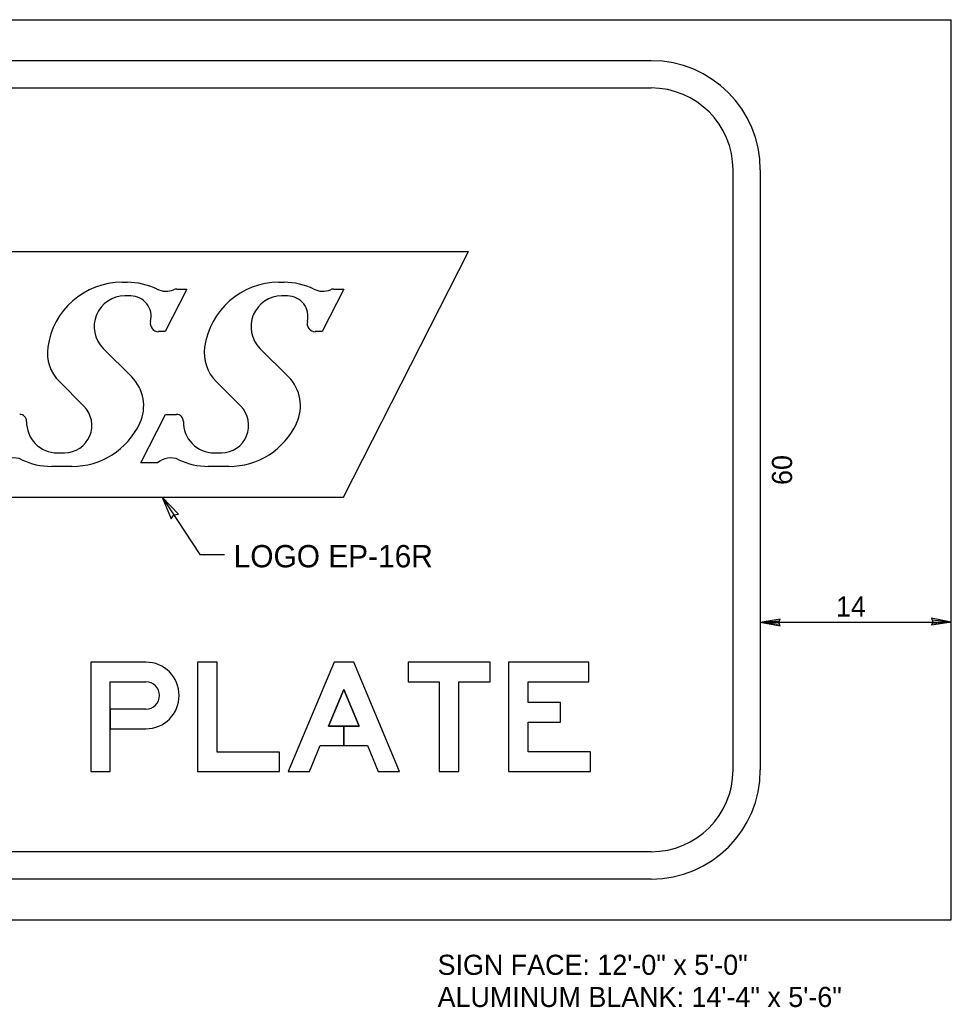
# Model space of a CAD drawing. Extents: x 60714 to 61340, y 9180 to 9758.
# Drawn here: x 60952.6 to 61082.4, y 9609.1 to 9746.7 of the extents above; entities that cross this region are included whole.
import ezdxf

# ---------------------------------------------------------------- set-up
doc = ezdxf.new("R2010")
doc.units = 0
for name, color, linetype in [('1', 7, 'Continuous'), ('2', 7, 'Continuous'), ('52', 7, 'Continuous'), ('GSBWFill', 7, 'Continuous'), ('SignPanel', 7, 'Continuous')]:
    doc.layers.add(name, color=color, linetype=linetype)

msp = doc.modelspace()

# ---------------------------------------------------------------- linework, layer by layer
at = {"layer": '1'}
for p, q in [((60972.45, 9680.2), (60977.68, 9672.2)), ((60977.68, 9672.2), (60981.12, 9672.2)), ((61055.78, 9662.78), (61082.38, 9662.78))]:
    msp.add_line(p, q, dxfattribs=at)
at = {"layer": '2'}
for p, q in [((60755.58, 9746.7), (61082.38, 9746.7)), ((61082.38, 9621.3), (61082.38, 9746.7)), ((60755.58, 9621.3), (61082.38, 9621.3))]:
    msp.add_line(p, q, dxfattribs=at)
at = {"layer": '52'}
for p, q in [((60972.45, 9680.2), (60973.69, 9677.16)), ((60974.71, 9677.83), (60972.45, 9680.2)), ((60973.69, 9677.16), (60974.08, 9677.71)), ((60974.08, 9677.71), (60974.71, 9677.83)), ((61055.78, 9662.78), (61058.56, 9663.22)), ((61058.34, 9662.73), (61058.56, 9663.22)), ((61082.38, 9662.78), (61079.62, 9663.31)), ((61079.62, 9663.31), (61079.83, 9662.82)), ((61055.78, 9662.78), (61058.44, 9662.96)), ((61055.78, 9662.78), (61058.54, 9662.24)), ((61055.78, 9662.78), (61058.44, 9662.5)), ((61058.54, 9662.24), (61058.34, 9662.73)), ((61079.83, 9662.82), (61079.61, 9662.34)), ((61082.38, 9662.78), (61079.61, 9662.34)), ((61082.38, 9662.78), (61079.72, 9662.59)), ((61082.38, 9662.78), (61079.73, 9663.06))]:
    msp.add_line(p, q, dxfattribs=at)
at = {"layer": 'GSBWFill'}
for p, q in [((60965.22, 9654.46), (60970.17, 9654.46)), ((60965.22, 9654.46), (60970.17, 9654.46)), ((60965.22, 9654.46), (60970.17, 9654.46)), ((60965.22, 9647.92), (60970.17, 9647.92))]:
    msp.add_line(p, q, dxfattribs=at)
for points in [[(60970.17, 9657.2), (60962.49, 9657.2), (60962.49, 9641.99), (60965.22, 9641.99), (60965.22, 9647.92)], [(60970.17, 9657.2), (60962.49, 9657.2), (60962.49, 9641.99), (60965.22, 9641.99), (60965.22, 9654.46)], [(60970.17, 9657.2), (60962.49, 9657.2), (60962.49, 9641.99), (60965.22, 9641.99), (60965.22, 9654.46)], [(60970.17, 9650.66), (60965.22, 9650.66), (60965.22, 9654.46)], [(60970.17, 9650.66), (60965.22, 9650.66), (60965.22, 9647.92), (60970.17, 9647.92)], [(60970.17, 9650.66), (60965.22, 9650.66), (60965.22, 9647.92), (60970.17, 9647.92)]]:
    msp.add_lwpolyline(points, dxfattribs=at)
for points in [[(60988.79, 9641.99), (60988.79, 9644.65), (60980.12, 9644.65), (60980.12, 9657.2), (60977.39, 9657.2), (60977.39, 9641.99)], [(60988.79, 9641.99), (60988.79, 9644.65), (60980.12, 9644.65), (60980.12, 9657.2), (60977.39, 9657.2), (60977.39, 9641.99)], [(60988.79, 9641.99), (60988.79, 9644.65), (60980.12, 9644.65), (60980.12, 9657.2), (60977.39, 9657.2), (60977.39, 9641.99)], [(60994.47, 9645.57), (61001.04, 9645.57), (61002.55, 9641.99), (61005.51, 9641.99), (60999.13, 9657.2), (60996.39, 9657.2), (60990.01, 9641.99), (60992.97, 9641.99)], [(60999.9, 9648.3), (60997.76, 9648.3), (60997.76, 9645.57), (61001.04, 9645.57), (61002.55, 9641.99), (61005.51, 9641.99), (60999.13, 9657.2), (60996.39, 9657.2), (60990.01, 9641.99), (60992.97, 9641.99), (60994.47, 9645.57), (60997.76, 9645.57), (60997.76, 9648.3), (60995.62, 9648.3), (60997.76, 9653.39)], [(60999.9, 9648.3), (60997.76, 9648.3), (60997.76, 9645.57), (61001.04, 9645.57), (61002.55, 9641.99), (61005.51, 9641.99), (60999.13, 9657.2), (60996.39, 9657.2), (60990.01, 9641.99), (60992.97, 9641.99), (60994.47, 9645.57), (60997.76, 9645.57), (60997.76, 9648.3), (60995.62, 9648.3), (60997.76, 9653.39)], [(61006.73, 9654.46), (61011.06, 9654.46), (61011.06, 9641.99), (61013.8, 9641.99), (61013.8, 9654.46), (61018.13, 9654.46), (61018.13, 9657.2), (61006.73, 9657.2)], [(61006.73, 9654.46), (61011.06, 9654.46), (61011.06, 9641.99), (61013.8, 9641.99), (61013.8, 9654.46), (61018.13, 9654.46), (61018.13, 9657.2), (61006.73, 9657.2)], [(61006.73, 9654.46), (61011.06, 9654.46), (61011.06, 9641.99), (61013.8, 9641.99), (61013.8, 9654.46), (61018.13, 9654.46), (61018.13, 9657.2), (61006.73, 9657.2)], [(61032.12, 9644.73), (61023.45, 9644.73), (61023.45, 9648.82), (61027.94, 9648.82), (61027.94, 9651.56), (61023.45, 9651.56), (61023.45, 9654.46), (61031.89, 9654.46), (61031.89, 9657.2), (61020.72, 9657.2), (61020.72, 9641.99), (61032.12, 9641.99)], [(61032.12, 9644.73), (61023.45, 9644.73), (61023.45, 9648.82), (61027.94, 9648.82), (61027.94, 9651.56), (61023.45, 9651.56), (61023.45, 9654.46), (61031.89, 9654.46), (61031.89, 9657.2), (61020.72, 9657.2), (61020.72, 9641.99), (61032.12, 9641.99)], [(61032.12, 9644.73), (61023.45, 9644.73), (61023.45, 9648.82), (61027.94, 9648.82), (61027.94, 9651.56), (61023.45, 9651.56), (61023.45, 9654.46), (61031.89, 9654.46), (61031.89, 9657.2), (61020.72, 9657.2), (61020.72, 9641.99), (61032.12, 9641.99)], [(60999.9, 9648.3), (60997.76, 9653.39), (60995.62, 9648.3)]]:
    msp.add_lwpolyline(points, close=True, dxfattribs=at)
for major_axis in [(0, 4.64), (0, 4.64), (0, 4.64), (0, 1.9), (0, 1.9), (0, 1.9)]:
    msp.add_ellipse((60970.17, 9652.56), major_axis=major_axis, ratio=0.999994, start_param=3.141593, end_param=6.283185, dxfattribs=at)
at = {"layer": 'SignPanel'}
for p, q in [((60797.38, 9741), (61040.59, 9741)), ((60797.38, 9737.2), (61040.59, 9737.2)), ((61051.99, 9642.2), (61051.99, 9725.8)), ((61055.79, 9642.2), (61055.79, 9725.8)), ((60906.74, 9714.4), (61015.12, 9714.4)), ((60997.7, 9680.2), (61015.12, 9714.4)), ((60966.86, 9710.12), (60967.58, 9710.12)), ((60988.71, 9710.12), (60989.43, 9710.12)), ((60975.9, 9709.17), (60972.88, 9703.25)), ((60974.47, 9709.17), (60975.9, 9709.17)), ((60997.75, 9709.17), (60994.73, 9703.25)), ((60996.32, 9709.17), (60997.75, 9709.17)), ((60968.06, 9708.22), (60967.25, 9708.22)), ((60989.91, 9708.22), (60989.1, 9708.22)), ((60972.88, 9703.25), (60971.93, 9703.25)), ((60994.73, 9703.25), (60993.78, 9703.25)), ((60964.22, 9700.92), (60968.2, 9696.94)), ((60986.07, 9700.92), (60990.06, 9696.94)), ((60961.54, 9692.86), (60958.12, 9696.28)), ((60983.39, 9692.86), (60979.97, 9696.28)), ((60969.48, 9684.95), (60972.93, 9691.72)), ((60972.93, 9691.72), (60974.45, 9691.72)), ((60957.82, 9686.37), (60958.85, 9686.37)), ((60979.68, 9686.37), (60980.7, 9686.37)), ((60959.87, 9684.47), (60957.02, 9684.47)), ((60971.78, 9684.95), (60969.48, 9684.95)), ((60981.72, 9684.47), (60978.86, 9684.47)), ((60904.22, 9680.2), (60997.7, 9680.2)), ((60797.38, 9630.8), (61040.59, 9630.8)), ((60797.38, 9627), (61040.59, 9627))]:
    msp.add_line(p, q, dxfattribs=at)
for centre, radius, start, end in [((61040.58, 9725.79), 15.2, 0, 90), ((61040.58, 9725.79), 11.4, 0, 90), ((60966.86, 9699.67), 10.45, 90, 172.3089), ((60967.58, 9700.62), 9.5, 64.0896, 90), ((60988.71, 9699.67), 10.45, 90, 172.3089), ((60989.43, 9700.62), 9.5, 64.0896, 90), ((60972.97, 9711.73), 2.85, 244.0896, 292.0347), ((60974.47, 9708.03), 1.14, 90, 112.0347), ((60994.82, 9711.73), 2.85, 244.0896, 292.0347), ((60996.32, 9708.03), 1.14, 90, 112.0347), ((60967.25, 9703.94), 4.28, 90, 225), ((60968.06, 9705.37), 2.85, 345.6915, 90), ((60989.1, 9703.94), 4.28, 90, 225), ((60989.91, 9705.37), 2.85, 345.6915, 90), ((60971.93, 9704.38), 1.14, 165.6915, 270), ((60993.78, 9704.38), 1.14, 165.6915, 270), ((60962.15, 9700.31), 5.7, 172.3089, 225), ((60984, 9700.31), 5.7, 172.3089, 225), ((60964.17, 9692.91), 5.7, 334.95, 45), ((60986.02, 9692.91), 5.7, 334.95, 45), ((60958.85, 9690.17), 3.8, 270, 45), ((60980.7, 9690.17), 3.8, 270, 45), ((60952.6, 9690.77), 0.95, 358.6664, 90), ((60957.83, 9690.64), 4.28, 178.6665, 270), ((60974.45, 9690.77), 0.95, 358.6664, 90), ((60979.68, 9690.64), 4.28, 178.6665, 270), ((60959.87, 9694.92), 10.45, 270, 334.95), ((60981.72, 9694.92), 10.45, 270, 334.95), ((60951.75, 9683.01), 2.66, 64.3795, 133.1892), ((60957.01, 9693.97), 9.5, 244.3795, 270), ((60973.61, 9683.01), 2.66, 64.3795, 133.1892), ((60978.86, 9693.97), 9.5, 244.3795, 270), ((61040.58, 9642.19), 15.2, 270, 360), ((61040.58, 9642.19), 11.4, 270, 0)]:
    msp.add_arc(centre, radius, start, end, dxfattribs=at)

# ---------------------------------------------------------------- texts
at = {"layer": '1'}
msp.add_text('60', height=2.8, rotation=90, dxfattribs=at).set_placement((61060.2, 9681.89))
for s, height, p in [('LOGO EP-16R', 3.1111, (60982.41, 9670.41)), ('14', 2.8, (61066.32, 9663.56))]:
    msp.add_text(s, height=height, dxfattribs=at).set_placement(p)
at = {"layer": '2'}
for s, p in [('SIGN FACE: 12\'-0" x 5\'-0"', (61010.82, 9613.64)), ('ALUMINUM BLANK: 14\'-4" x 5\'-6"', (61010.82, 9609.16))]:
    msp.add_text(s, height=2.8, dxfattribs=at).set_placement(p)

doc.saveas('drawing.dxf')
